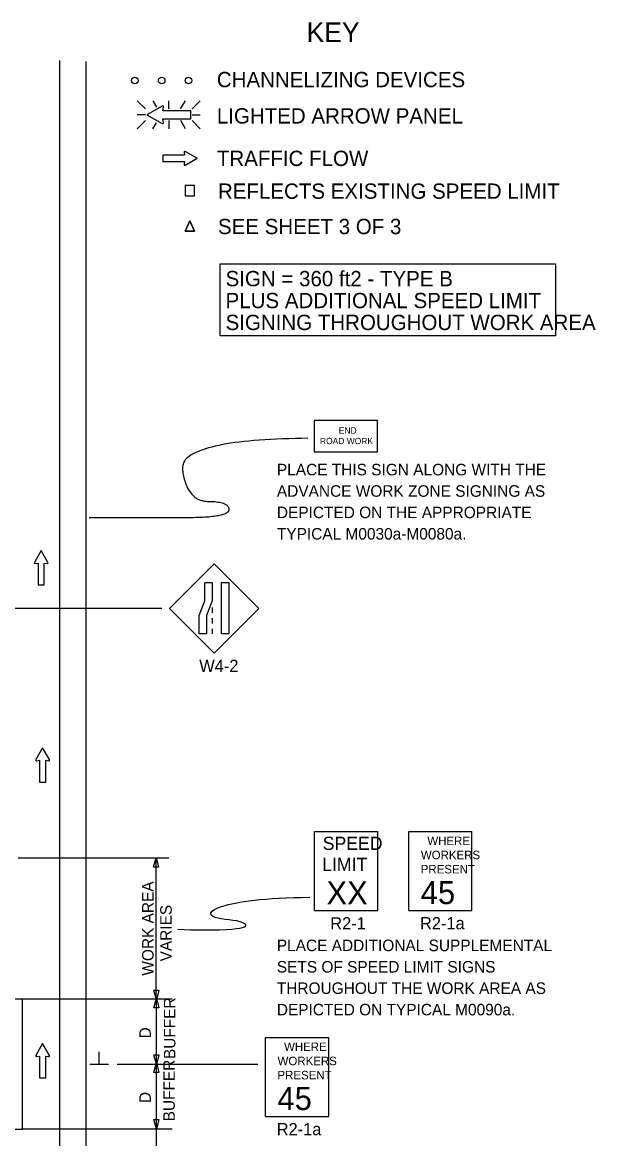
# Model space of a CAD drawing. Extents: x 20837 to 23689, y 414 to 2167.
# Drawn here: x 21275 to 21623, y 983 to 1661 of the extents above; entities that cross this region are included whole.
import ezdxf

# ---------------------------------------------------------------- set-up
doc = ezdxf.new("R2010")
doc.units = 0
for name, color, linetype in [('ALI_LEGAL_EX', 7, 'Continuous'), ('MT_SCRATCH_LEVEL_E', 7, 'Continuous'), ('PAVT_EDGE_EX', 7, 'Continuous'), ('TRAFFIC_SIGNS_PR', 7, 'Continuous'), ('TYPICAL_TEXT_DIMEN_EX', 7, 'Continuous'), ('TYPICAL_TEXT_DIMEN_PR', 7, 'Continuous')]:
    doc.layers.add(name, color=color, linetype=linetype)

msp = doc.modelspace()

# ---------------------------------------------------------------- linework, layer by layer
at = {"layer": 'ALI_LEGAL_EX'}
msp.add_lwpolyline([(21274.98, 1033.66), (21274.98, 1059.07)], dxfattribs=at)
at = {"layer": 'MT_SCRATCH_LEVEL_E'}
for p, q in [((21373.27, 1579.9), (21360.02, 1579.9)), ((21360.02, 1579.9), (21360.02, 1576.16)), ((21373.27, 1579.9), (21360.02, 1579.9)), ((21360.02, 1579.9), (21360.02, 1576.16)), ((21372.96, 1581.68), (21373.27, 1579.9)), ((21372.96, 1581.68), (21373.27, 1579.9)), ((21380.88, 1578.05), (21373.64, 1582.16)), ((21380.88, 1578.05), (21373.64, 1582.16)), ((21360.02, 1576.16), (21373.27, 1576.16)), ((21360.02, 1576.16), (21373.27, 1576.16)), ((21373.27, 1576.16), (21372.96, 1574.38)), ((21373.27, 1576.16), (21372.96, 1574.38)), ((21373.64, 1573.91), (21380.88, 1578.05)), ((21373.64, 1573.91), (21380.88, 1578.05)), ((21286.24, 1339.82), (21282.13, 1332.58)), ((21286.24, 1339.82), (21282.13, 1332.58)), ((21290.39, 1332.58), (21286.24, 1339.82)), ((21290.39, 1332.58), (21286.24, 1339.82)), ((21282.61, 1331.89), (21284.39, 1332.21)), ((21282.61, 1331.89), (21284.39, 1332.21)), ((21284.39, 1332.21), (21284.39, 1318.95)), ((21284.39, 1332.21), (21284.39, 1318.95)), ((21288.13, 1318.95), (21288.13, 1332.21)), ((21288.13, 1332.21), (21289.91, 1331.89)), ((21288.13, 1318.95), (21288.13, 1332.21)), ((21288.13, 1332.21), (21289.91, 1331.89)), ((21284.39, 1318.95), (21288.13, 1318.95)), ((21284.39, 1318.95), (21288.13, 1318.95)), ((21287.14, 1220.1), (21283.03, 1212.86)), ((21287.14, 1220.1), (21283.03, 1212.86)), ((21291.29, 1212.86), (21287.14, 1220.1)), ((21291.29, 1212.86), (21287.14, 1220.1)), ((21283.51, 1212.18), (21285.29, 1212.49)), ((21283.51, 1212.18), (21285.29, 1212.49)), ((21285.29, 1212.49), (21285.29, 1199.23)), ((21285.29, 1212.49), (21285.29, 1199.23)), ((21289.03, 1199.23), (21289.03, 1212.49)), ((21289.03, 1212.49), (21290.81, 1212.18)), ((21289.03, 1199.23), (21289.03, 1212.49)), ((21289.03, 1212.49), (21290.81, 1212.18)), ((21285.29, 1199.23), (21289.03, 1199.23)), ((21285.29, 1199.23), (21289.03, 1199.23)), ((21287.14, 1040.44), (21283.03, 1033.2)), ((21287.14, 1040.44), (21283.03, 1033.2)), ((21291.29, 1033.2), (21287.14, 1040.44)), ((21291.29, 1033.2), (21287.14, 1040.44)), ((21283.51, 1032.51), (21285.29, 1032.83)), ((21283.51, 1032.51), (21285.29, 1032.83)), ((21285.29, 1032.83), (21285.29, 1019.57)), ((21285.29, 1032.83), (21285.29, 1019.57)), ((21289.03, 1019.57), (21289.03, 1032.83)), ((21289.03, 1032.83), (21290.81, 1032.51)), ((21289.03, 1019.57), (21289.03, 1032.83)), ((21289.03, 1032.83), (21290.81, 1032.51)), ((21285.29, 1019.57), (21289.03, 1019.57)), ((21285.29, 1019.57), (21289.03, 1019.57))]:
    msp.add_line(p, q, dxfattribs=at)
for centre, start, end in [((21373.42, 1581.76), 60.42484, 189.96381), ((21373.42, 1581.76), 60.42484, 189.96381), ((21373.42, 1574.32), 170.03619, 299.77312), ((21373.42, 1574.32), 170.03619, 299.77312), ((21282.54, 1332.35), 150.42484, 279.96381), ((21282.54, 1332.35), 150.42484, 279.96381), ((21289.98, 1332.35), 260.03619, 29.77312), ((21289.98, 1332.35), 260.03619, 29.77312), ((21283.44, 1212.63), 150.42484, 279.96381), ((21283.44, 1212.63), 150.42484, 279.96381), ((21290.88, 1212.64), 260.03619, 29.77312), ((21290.88, 1212.64), 260.03619, 29.77312), ((21283.44, 1032.97), 150.42484, 279.96381), ((21283.44, 1032.97), 150.42484, 279.96381), ((21290.88, 1032.97), 260.03619, 29.77312), ((21290.88, 1032.97), 260.03619, 29.77312)]:
    msp.add_arc(centre, 0.463, start, end, dxfattribs=at)
at = {"layer": 'PAVT_EDGE_EX'}
for p, q in [((21297.4, 1637.35), (21297.4, 813.35)), ((21313.4, 1636.75), (21313.4, 813.35))]:
    msp.add_line(p, q, dxfattribs=at)
msp.add_lwpolyline([(21274.98, 1067.27), (21200.14, 1067.27), (21200.14, 988.38), (21274.98, 988.38)], close=True, dxfattribs=at)
at = {"layer": 'TRAFFIC_SIGNS_PR'}
for p, q in [((21344.56, 1612.99), (21349.5, 1608.06)), ((21356.33, 1609.17), (21354.12, 1612.99)), ((21363.65, 1608.06), (21363.65, 1612.99)), ((21370.88, 1608.06), (21373.73, 1612.99)), ((21377.8, 1608.06), (21382.73, 1612.99)), ((21349.5, 1604.5), (21344.56, 1604.5)), ((21344.56, 1596.01), (21349.5, 1600.95)), ((21363.65, 1600.95), (21363.65, 1596.01)), ((21373.78, 1596.01), (21370.93, 1600.95)), ((21377.8, 1604.5), (21382.73, 1604.5)), ((21377.8, 1600.95), (21382.73, 1596.01)), ((21354.08, 1596.01), (21356.19, 1599.67)), ((21391.2, 1331.82), (21364.05, 1304.67)), ((21418.36, 1304.67), (21391.2, 1331.82)), ((21364.05, 1304.67), (21391.2, 1277.52)), ((21389.96, 1305.16), (21389.96, 1301.96)), ((21391.2, 1277.52), (21418.36, 1304.67)), ((21389.96, 1298.76), (21389.96, 1295.56)), ((21389.96, 1292.36), (21389.96, 1289.16)), ((21452.03, 1169.14), (21490.43, 1169.14)), ((21452.03, 1121.14), (21452.03, 1169.14)), ((21490.43, 1121.14), (21490.43, 1169.14)), ((21509.23, 1169.23), (21547.63, 1169.23)), ((21509.23, 1121.23), (21509.23, 1169.23)), ((21547.63, 1121.23), (21547.63, 1169.23)), ((21452.03, 1121.14), (21490.43, 1121.14)), ((21509.23, 1121.23), (21547.63, 1121.23)), ((21422.31, 1044.16), (21460.71, 1044.16)), ((21422.31, 996.16), (21422.31, 1044.16)), ((21460.71, 996.16), (21460.71, 1044.16)), ((21422.31, 996.16), (21460.71, 996.16))]:
    msp.add_line(p, q, dxfattribs=at)
for points in [[(21359.57, 1609.78), (21350.28, 1604.5), (21359.58, 1599.18)], [(21360.45, 1599.81), (21360.05, 1602.08), (21377.06, 1602.08), (21377.06, 1606.88), (21360.05, 1606.88), (21360.45, 1609.16)], [(21376.48, 1539.98), (21373.69, 1533.81)], [(21373.69, 1533.81), (21376.48, 1539.98)], [(21379.28, 1533.81), (21376.48, 1539.98)], [(21376.48, 1539.98), (21379.28, 1533.81)], [(21373.69, 1533.81), (21379.28, 1533.81)], [(21379.28, 1533.81), (21373.69, 1533.81)]]:
    msp.add_lwpolyline(points, dxfattribs=at)
for points in [[(21373.69, 1555.28), (21379.28, 1555.28), (21379.28, 1561.45), (21373.69, 1561.45)], [(21451.82, 1399.69), (21490.22, 1399.69), (21490.22, 1418.89), (21451.82, 1418.89)], [(21389.96, 1320.4), (21389.96, 1309.22), (21386.61, 1300.34), (21386.61, 1289.16), (21382.12, 1289.16), (21382.12, 1300.34), (21385.46, 1309.22), (21385.46, 1320.4)], [(21400.09, 1320.4), (21400.09, 1289.16), (21395.6, 1289.16), (21395.6, 1320.4)]]:
    msp.add_lwpolyline(points, close=True, dxfattribs=at)
for centre in [(21343.07, 1625.34), (21359.37, 1625.34), (21375.67, 1625.34)]:
    msp.add_circle(centre, 2, dxfattribs=at)
for centre, radius, start, end in [((21359.86, 1609.25), 0.598, 350.73078, 118.89165), ((21359.86, 1599.71), 0.597, 241.48329, 9.95933)]:
    msp.add_arc(centre, radius, start, end, dxfattribs=at)
at = {"layer": 'TYPICAL_TEXT_DIMEN_EX'}
msp.add_lwpolyline([(21394.79, 1514.03), (21598.35, 1514.03), (21598.35, 1470.26), (21394.79, 1470.26)], close=True, dxfattribs=at)
at = {"layer": 'TYPICAL_TEXT_DIMEN_PR'}
for p, q in [((21359.37, 1304.61), (21201.93, 1304.61)), ((21272.32, 1153.17), (21363.75, 1153.17)), ((21354.38, 1147.55), (21355.95, 1153.41)), ((21355.95, 1153.41), (21357.52, 1147.55)), ((21355.95, 1147.55), (21354.38, 1147.55)), ((21355.95, 1067.65), (21355.95, 1151.96)), ((21357.52, 1147.55), (21355.95, 1147.55)), ((21356.13, 1066.93), (21354.56, 1072.79)), ((21354.56, 1072.79), (21356.13, 1072.79)), ((21356.13, 1072.79), (21357.7, 1072.79)), ((21357.7, 1072.79), (21356.13, 1066.93)), ((21365.67, 1067.27), (21200.14, 1067.27)), ((21354.56, 1062.08), (21356.14, 1067.94)), ((21356.14, 1067.94), (21357.71, 1062.08)), ((21356.14, 1027.66), (21356.14, 1067.66)), ((21356.14, 1062.08), (21354.56, 1062.08)), ((21357.71, 1062.08), (21356.14, 1062.08)), ((21321.45, 1027.62), (21321.45, 1035.4)), ((21356.14, 1027.66), (21354.57, 1033.52)), ((21354.57, 1033.52), (21356.14, 1033.52)), ((21356.14, 1033.52), (21357.71, 1033.52)), ((21357.71, 1033.52), (21356.14, 1027.66)), ((21327.07, 1027.62), (21315.82, 1027.62)), ((21417.68, 1027.66), (21332.46, 1027.66)), ((21354.57, 1022.81), (21356.14, 1028.67)), ((21356.14, 1028.67), (21357.71, 1022.81)), ((21356.14, 988.38), (21356.14, 1028.38)), ((21356.14, 1022.81), (21354.57, 1022.81)), ((21357.71, 1022.81), (21356.14, 1022.81)), ((21356.14, 988.38), (21354.57, 994.25)), ((21354.57, 994.25), (21356.14, 994.25)), ((21356.14, 994.25), (21357.71, 994.25)), ((21357.71, 994.25), (21356.14, 988.38)), ((21365.67, 988.38), (21274.98, 988.38)), ((21356.14, 953.77), (21356.14, 988.38))]:
    msp.add_line(p, q, dxfattribs=at)
for points, degree in [([(21448.09, 1408.04), (21368.87, 1407.07), (21375, 1369.67), (21400.18, 1369.67), (21400.18, 1359.76), (21350.53, 1359.76), (21315.47, 1359.76)], 2), ([(21369.16, 1109.79), (21412.86, 1108.33), (21412.86, 1115.59), (21387.68, 1115.59), (21387.68, 1123.89), (21421.72, 1129.06), (21449.34, 1129.24)], 3)]:
    msp.add_open_spline(points, degree=degree, dxfattribs=at)

# ---------------------------------------------------------------- texts
at = {"layer": 'TRAFFIC_SIGNS_PR'}
for s, height, p in [('END', 3.831, (21466.82, 1410.82)), ('ROAD WORK', 3.831, (21455.43, 1404.43)), ('PLACE THIS SIGN ALONG WITH THE', 7, (21429.27, 1385.49)), ('ADVANCE WORK ZONE SIGNING AS', 7, (21429.27, 1372.49)), ('DEPICTED ON THE APPROPRIATE', 7, (21429.27, 1359.49)), ('TYPICAL M0030a-M0080a.', 7, (21429.27, 1346.49)), ('W4-2', 7.44, (21382.16, 1266.08)), ('SPEED', 8, (21457.07, 1158.01)), ('WHERE', 5.2, (21520.54, 1160.92)), ('LIMIT', 8, (21456.74, 1145.21)), ('WORKERS', 5.2, (21516.61, 1152.32)), ('PRESENT', 5.2, (21516.55, 1143.72)), ('45', 14.031, (21516.54, 1125.09)), ('XX', 14.031, (21459.34, 1124.9)), ('R2-1', 7.44, (21461.64, 1109.7)), ('R2-1a', 7.44, (21516.08, 1109.79)), ('PLACE ADDITIONAL SUPPLEMENTAL', 7, (21429.23, 1096.53)), ('SETS OF SPEED LIMIT SIGNS', 7, (21429.23, 1083.53)), ('THROUGHOUT THE WORK AREA AS', 7, (21429.23, 1070.53)), ('DEPICTED ON TYPICAL M0090a.', 7, (21429.23, 1057.53)), ('WHERE', 5.2, (21433.62, 1035.84)), ('WORKERS', 5.2, (21429.69, 1027.24)), ('PRESENT', 5.2, (21429.62, 1018.64)), ('45', 14.031, (21429.61, 1000.01)), ('R2-1a', 7.44, (21429.16, 984.72))]:
    msp.add_text(s, height=height, dxfattribs=at).set_placement(p)
at = {"layer": 'TYPICAL_TEXT_DIMEN_EX'}
for s, height, p in [('KEY', 12, (21447.32, 1648.62)), ('CHANNELIZING DEVICES', 9.3, (21392.85, 1621.21)), ('LIGHTED ARROW PANEL', 9.3, (21392.85, 1599.16)), ('TRAFFIC FLOW', 9.3, (21392.85, 1573.36)), ('REFLECTS EXISTING SPEED LIMIT', 9.3, (21393.52, 1553.44)), ('SEE SHEET 3 OF 3', 9.3, (21393.52, 1531.97)), ('SIGN = 360 ft2 - TYPE B', 9.3, (21398.13, 1500.32)), ('PLUS ADDITIONAL SPEED LIMIT', 9.3, (21398.13, 1487.02)), ('SIGNING THROUGHOUT WORK AREA', 9.3, (21398.13, 1473.72))]:
    msp.add_text(s, height=height, dxfattribs=at).set_placement(p)
at = {"layer": 'TYPICAL_TEXT_DIMEN_PR'}
for s, p in [('WORK AREA', (21354.48, 1081.67)), ('VARIES', (21365.48, 1090.31)), ('BUFFER', (21367.7, 1030.99)), ('D', (21352.82, 1043.54)), ('BUFFER', (21367.34, 993.17)), ('D', (21352.82, 1004.27))]:
    msp.add_text(s, height=7, rotation=90, dxfattribs=at).set_placement(p)

doc.saveas('drawing.dxf')
